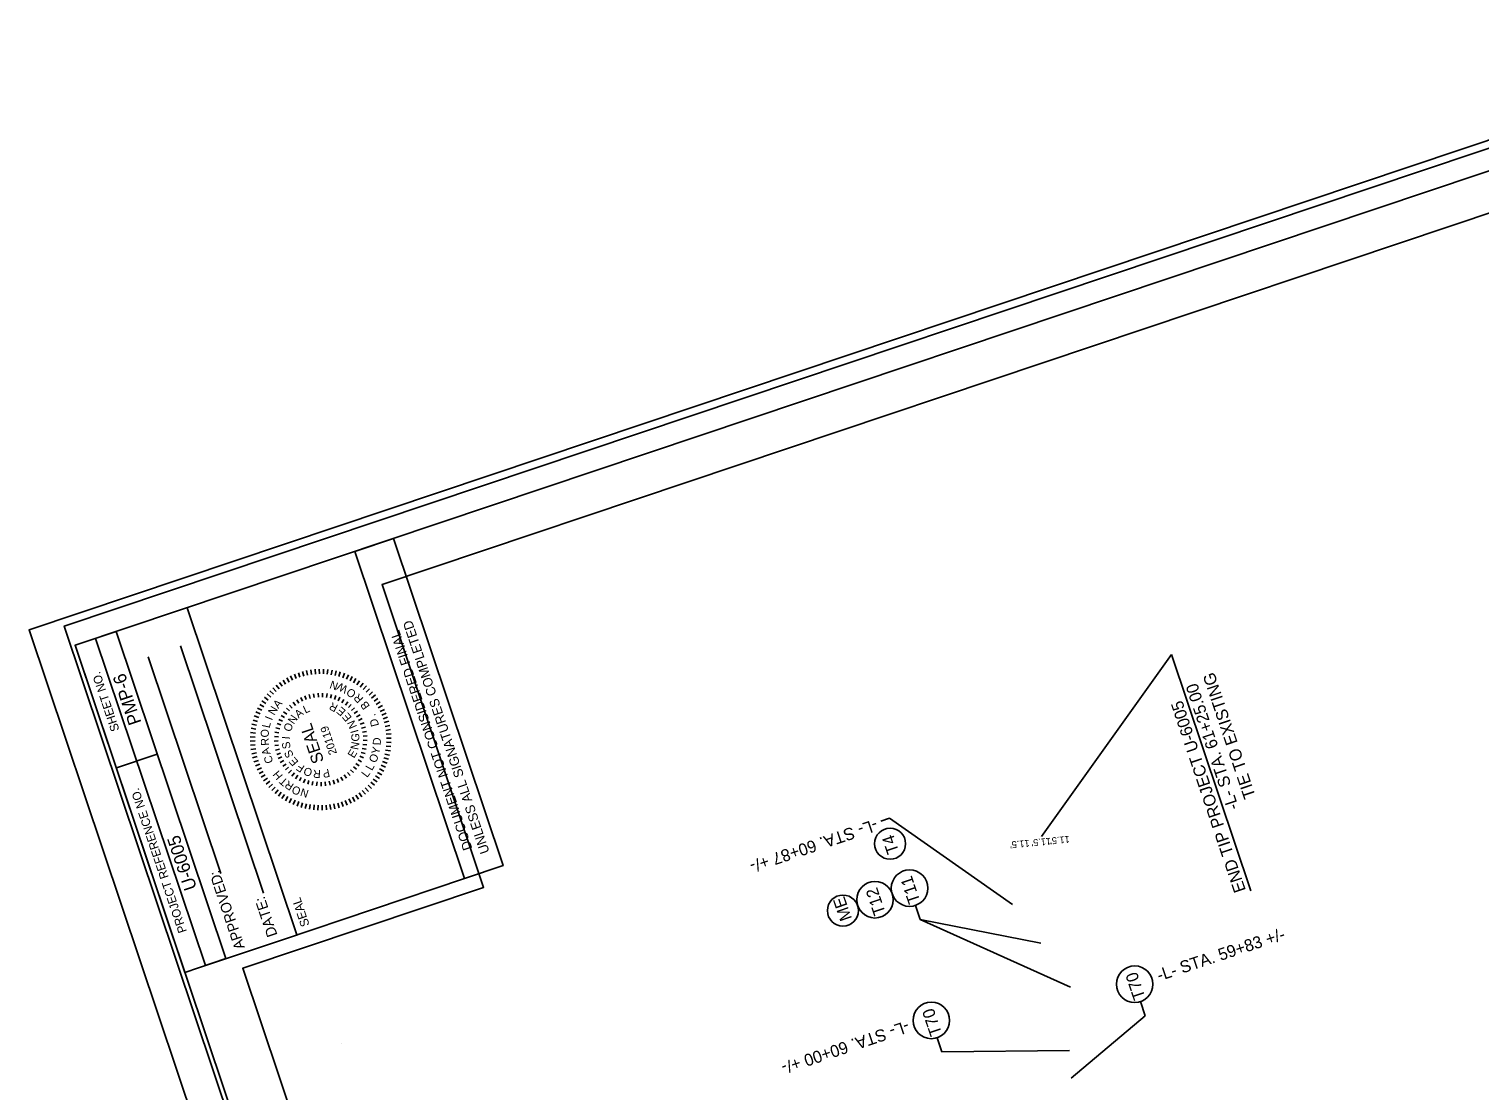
# Model space of a CAD drawing. Extents: x 1615436 to 1617119, y 903110 to 905145.
# Drawn here: x 1615436 to 1616278, y 904439 to 905055 of the extents above; entities that cross this region are included whole.
import ezdxf

# ---------------------------------------------------------------- set-up
doc = ezdxf.new("R2010")
doc.units = 0
for name, color, linetype in [('DEV BORDER CELL', 7, 'Continuous'), ('Old_Level_10', 7, 'Continuous'), ('Old_Level_4', 7, 'Continuous'), ('Prop Horizontal Alignment Curve and Spiral Data', 7, 'Continuous'), ('Prop Horizontal Alignment Station Label', 7, 'Continuous'), ('Sheet Data Field CELL', 7, 'Continuous'), ('Sheet Layout Plan Border', 7, 'Continuous'), ('Sheet North Arrow Point CELL', 7, 'Continuous'), ('Sheet Plan CELL', 7, 'Continuous'), ('Sheet Plot Border Inside CELL', 7, 'Continuous'), ('Sheet Plot Border Outside CELL', 7, 'Continuous'), ('Sheet Sticker Exception Certification CELL', 7, 'Continuous'), ('Sheet Title CELL', 7, 'Continuous'), ('Text', 7, 'Continuous')]:
    doc.layers.add(name, color=color, linetype=linetype)

msp = doc.modelspace()

# ---------------------------------------------------------------- linework, layer by layer
at = {"layer": 'DEV BORDER CELL'}
for p, q in [((1615599.8, 904683.37), (1615600.2, 904680.61)), ((1615602.25, 904683.64), (1615602.48, 904680.87)), ((1615604.72, 904683.77), (1615604.78, 904680.98)), ((1615607.19, 904683.75), (1615607.08, 904680.96)), ((1615609.65, 904683.57), (1615609.38, 904680.8)), ((1615581.65, 904676.06), (1615583.28, 904673.79)), ((1615583.7, 904677.44), (1615585.19, 904675.08)), ((1615585.83, 904678.7), (1615587.17, 904676.26)), ((1615588.02, 904679.82), (1615589.22, 904677.31)), ((1615590.28, 904680.81), (1615591.32, 904678.23)), ((1615592.6, 904681.67), (1615593.49, 904679.02)), ((1615594.97, 904682.38), (1615595.69, 904679.69)), ((1615597.37, 904682.95), (1615597.93, 904680.22)), ((1615612.1, 904683.25), (1615611.66, 904680.5)), ((1615614.53, 904682.78), (1615613.91, 904680.07)), ((1615616.92, 904682.17), (1615616.14, 904679.49)), ((1615619.27, 904681.41), (1615618.33, 904678.79)), ((1615621.57, 904680.51), (1615620.48, 904677.95)), ((1615623.81, 904679.48), (1615622.57, 904676.99)), ((1615625.98, 904678.31), (1615624.59, 904675.9)), ((1615628.09, 904677.01), (1615626.55, 904674.69)), ((1615630.1, 904675.59), (1615628.43, 904673.36)), ((1615572.87, 904667.44), (1615575.1, 904665.77)), ((1615574.41, 904669.37), (1615576.54, 904667.57)), ((1615576.07, 904671.2), (1615578.08, 904669.27)), ((1615577.84, 904672.93), (1615579.72, 904670.88)), ((1615579.7, 904674.55), (1615581.46, 904672.39)), ((1615594, 904667.24), (1615595, 904665.14)), ((1615596.41, 904668.24), (1615597.2, 904666.06)), ((1615598.89, 904669), (1615599.47, 904666.76)), ((1615601.72, 904667.22), (1615601.36, 904669.51)), ((1615604.04, 904669.8), (1615604.17, 904667.48)), ((1615606.64, 904669.82), (1615606.55, 904667.5)), ((1615609.23, 904669.59), (1615608.91, 904667.29)), ((1615611.79, 904669.11), (1615611.25, 904666.85)), ((1615614.29, 904668.39), (1615613.54, 904666.19)), ((1615616.71, 904667.43), (1615615.75, 904665.32)), ((1615632.03, 904674.05), (1615630.23, 904671.93)), ((1615633.87, 904672.4), (1615631.94, 904670.38)), ((1615635.59, 904670.63), (1615633.55, 904668.74)), ((1615637.22, 904668.77), (1615635.06, 904667)), ((1615638.72, 904666.81), (1615636.46, 904665.18)), ((1615567.95, 904658.91), (1615570.52, 904657.81)), ((1615568.99, 904661.15), (1615571.48, 904659.9)), ((1615570.16, 904663.32), (1615572.57, 904661.93)), ((1615571.45, 904665.42), (1615573.78, 904663.89)), ((1615584.02, 904659.08), (1615585.88, 904657.68)), ((1615585.68, 904661.08), (1615587.4, 904659.51)), ((1615587.53, 904662.91), (1615589.08, 904661.19)), ((1615589.55, 904664.56), (1615590.92, 904662.69)), ((1615591.71, 904666.01), (1615592.9, 904664.01)), ((1615619.02, 904666.24), (1615617.86, 904664.23)), ((1615621.21, 904664.83), (1615619.86, 904662.94)), ((1615623.26, 904663.22), (1615621.73, 904661.47)), ((1615625.13, 904661.41), (1615623.45, 904659.82)), ((1615626.83, 904659.44), (1615625, 904658.01)), ((1615640.1, 904664.76), (1615637.75, 904663.28)), ((1615641.36, 904662.64), (1615638.92, 904661.3)), ((1615642.48, 904660.44), (1615639.97, 904659.25)), ((1615643.48, 904658.18), (1615640.89, 904657.14)), ((1615565.68, 904651.86), (1615568.4, 904651.25)), ((1615566.3, 904654.26), (1615568.97, 904653.48)), ((1615567.05, 904656.6), (1615569.68, 904655.67)), ((1615579.51, 904649.76), (1615581.76, 904649.17)), ((1615580.29, 904652.24), (1615582.48, 904651.43)), ((1615581.31, 904654.63), (1615583.41, 904653.62)), ((1615582.56, 904656.92), (1615584.54, 904655.71)), ((1615628.33, 904657.31), (1615626.36, 904656.07)), ((1615629.61, 904655.05), (1615627.54, 904654)), ((1615630.67, 904652.67), (1615628.51, 904651.83)), ((1615631.5, 904650.2), (1615629.26, 904649.57)), ((1615644.33, 904655.86), (1615641.69, 904654.98)), ((1615645.04, 904653.5), (1615642.35, 904652.78)), ((1615645.61, 904651.1), (1615642.88, 904650.54)), ((1615564.7, 904642.06), (1615567.49, 904642.12)), ((1615564.72, 904644.53), (1615567.51, 904644.41)), ((1615564.9, 904646.99), (1615567.67, 904646.71)), ((1615565.21, 904649.44), (1615567.97, 904648.99)), ((1615578.64, 904642.02), (1615580.96, 904642.1)), ((1615578.68, 904644.62), (1615581, 904644.48)), ((1615578.97, 904647.21), (1615581.26, 904646.84)), ((1615632.08, 904647.67), (1615629.8, 904647.25)), ((1615630.1, 904644.88), (1615632.42, 904645.07)), ((1615632.5, 904642.48), (1615630.18, 904642.52)), ((1615646.03, 904648.67), (1615643.28, 904648.27)), ((1615646.31, 904646.21), (1615643.53, 904645.98)), ((1615646.41, 904641.28), (1615643.62, 904641.39)), ((1615646.43, 904643.74), (1615643.64, 904643.68)), ((1615564.82, 904639.59), (1615567.6, 904639.82)), ((1615565.1, 904637.14), (1615567.85, 904637.53)), ((1615565.52, 904634.71), (1615568.25, 904635.27)), ((1615566.09, 904632.3), (1615568.78, 904633.03)), ((1615578.85, 904639.42), (1615581.15, 904639.73)), ((1615579.31, 904636.87), (1615581.57, 904637.38)), ((1615580.02, 904634.36), (1615582.22, 904635.09)), ((1615582.22, 904635.09), (1615580.02, 904634.36)), ((1615580.96, 904631.93), (1615583.08, 904632.88)), ((1615630.35, 904632.35), (1615628.22, 904633.26)), ((1615631.26, 904634.8), (1615629.04, 904635.49)), ((1615631.92, 904637.31), (1615629.65, 904637.8)), ((1615632.33, 904639.88), (1615630.02, 904640.14)), ((1615645.45, 904633.94), (1615642.73, 904634.55)), ((1615645.92, 904636.37), (1615643.16, 904636.81)), ((1615646.23, 904638.81), (1615643.46, 904639.09)), ((1615566.8, 904629.94), (1615569.44, 904630.82)), ((1615567.65, 904627.62), (1615570.24, 904628.66)), ((1615568.65, 904625.36), (1615571.16, 904626.55)), ((1615569.77, 904623.16), (1615572.21, 904624.51)), ((1615582.13, 904629.61), (1615584.15, 904630.75)), ((1615583.52, 904627.41), (1615585.43, 904628.74)), ((1615585.12, 904625.35), (1615586.89, 904626.87)), ((1615586.91, 904623.46), (1615588.52, 904625.14)), ((1615624.55, 904623.79), (1615622.91, 904625.43)), ((1615626.3, 904625.7), (1615624.52, 904627.19)), ((1615627.87, 904627.79), (1615625.95, 904629.09)), ((1615629.22, 904630.01), (1615627.18, 904631.12)), ((1615642.14, 904624.66), (1615639.65, 904625.9)), ((1615643.18, 904626.9), (1615640.61, 904627.99)), ((1615644.08, 904629.2), (1615641.45, 904630.13)), ((1615644.83, 904631.55), (1615642.16, 904632.32)), ((1615571.03, 904621.04), (1615573.38, 904622.53)), ((1615572.41, 904618.99), (1615574.67, 904620.62)), ((1615573.91, 904617.03), (1615576.07, 904618.8)), ((1615575.54, 904615.17), (1615577.58, 904617.06)), ((1615588.88, 904621.75), (1615590.32, 904623.58)), ((1615591, 904620.24), (1615592.25, 904622.2)), ((1615593.25, 904618.94), (1615594.31, 904621.01)), ((1615595.62, 904617.87), (1615596.48, 904620.02)), ((1615598.08, 904617.02), (1615598.73, 904619.25)), ((1615600.61, 904616.42), (1615601.04, 904618.7)), ((1615603.2, 904616.06), (1615603.4, 904618.38)), ((1615605.8, 904615.96), (1615605.77, 904618.29)), ((1615608.39, 904616.11), (1615608.15, 904618.42)), ((1615610.97, 904616.51), (1615610.5, 904618.78)), ((1615613.49, 904617.15), (1615612.81, 904619.37)), ((1615615.94, 904618.04), (1615615.05, 904620.18)), ((1615618.29, 904619.16), (1615617.19, 904621.2)), ((1615620.52, 904620.49), (1615619.24, 904622.42)), ((1615622.62, 904622.04), (1615621.15, 904623.84)), ((1615635.06, 904614.6), (1615633.05, 904616.53)), ((1615636.72, 904616.43), (1615634.59, 904618.24)), ((1615638.26, 904618.36), (1615636.03, 904620.03)), ((1615639.68, 904620.38), (1615637.35, 904621.92)), ((1615640.97, 904622.48), (1615638.56, 904623.87)), ((1615577.26, 904613.41), (1615579.19, 904615.42)), ((1615579.1, 904611.75), (1615580.9, 904613.88)), ((1615581.03, 904610.21), (1615582.7, 904612.44)), ((1615583.04, 904608.79), (1615584.58, 904611.11)), ((1615585.15, 904607.49), (1615586.54, 904609.91)), ((1615587.32, 904606.33), (1615588.56, 904608.82)), ((1615589.56, 904605.29), (1615590.65, 904607.85)), ((1615620.85, 904604.99), (1615619.81, 904607.57)), ((1615623.11, 904605.98), (1615621.91, 904608.5)), ((1615625.3, 904607.11), (1615623.96, 904609.55)), ((1615627.43, 904608.36), (1615625.94, 904610.72)), ((1615629.48, 904609.75), (1615627.85, 904612.01)), ((1615631.43, 904611.25), (1615629.67, 904613.41)), ((1615633.29, 904612.87), (1615631.41, 904614.92)), ((1615591.86, 904604.39), (1615592.8, 904607.02)), ((1615594.21, 904603.63), (1615594.99, 904606.31)), ((1615596.6, 904603.02), (1615597.22, 904605.74)), ((1615599.03, 904602.55), (1615599.47, 904605.3)), ((1615601.48, 904602.23), (1615601.75, 904605)), ((1615603.94, 904602.06), (1615604.05, 904604.84)), ((1615606.41, 904602.03), (1615606.35, 904604.82)), ((1615608.88, 904602.16), (1615608.65, 904604.94)), ((1615611.33, 904602.43), (1615610.93, 904605.19)), ((1615613.76, 904602.86), (1615613.2, 904605.58)), ((1615616.16, 904603.42), (1615615.44, 904606.11)), ((1615618.53, 904604.14), (1615617.64, 904606.78))]:
    msp.add_line(p, q, dxfattribs=at)
at = {"layer": 'Old_Level_10'}
for p, q in [((1615572.45, 904553.86), (1615524.33, 904697.3)), ((1615547.63, 904565.24), (1615505.46, 904690.97))]:
    msp.add_line(p, q, dxfattribs=at)
at = {"layer": 'Prop Horizontal Alignment Curve and Spiral Data'}
msp.add_line((1616144.77, 904555.27), (1616098.85, 904692.18), dxfattribs=at)
at = {"layer": 'Prop Horizontal Alignment Station Label'}
msp.add_line((1616023.42, 904586.81), (1616098.85, 904692.18), dxfattribs=at)
at = {"layer": 'Sheet Layout Plan Border'}
msp.add_lwpolyline([(1616672.58, 903656.2), (1616919.77, 903656.8), (1616590.65, 904611.24), (1616386.84, 904624.44), (1616334.81, 904821.64), (1616466, 905009.57), (1615641.09, 904732.87), (1615700.02, 904557.19), (1615560.35, 904510.33), (1615954.19, 903336.21)], close=True, dxfattribs=at)
at = {"layer": 'Sheet North Arrow Point CELL'}
msp.add_line((1615617.56, 904466.62), (1615617.56, 904466.62), dxfattribs=at)
at = {"layer": 'Sheet Plan CELL'}
for p, q in [((1615538.66, 904511.93), (1615475.05, 904701.6)), ((1615550.54, 904515.93), (1615486.9, 904705.57)), ((1615550.54, 904515.93), (1615486.9, 904705.57)), ((1615487.07, 904626.5), (1615510.76, 904634.49))]:
    msp.add_line(p, q, dxfattribs=at)
for points in [[(1615463.14, 904697.64), (1615940.18, 903275.48), (1616935.67, 903609.4), (1616458.64, 905031.54)], [(1615526.76, 904507.95), (1615463.14, 904697.64), (1615486.9, 904705.57), (1615550.54, 904515.93)]]:
    msp.add_lwpolyline(points, close=True, dxfattribs=at)
at = {"layer": 'Sheet Plot Border Inside CELL'}
msp.add_lwpolyline([(1616986.86, 903464.68), (1616457.04, 905044.17), (1615456.82, 904708.68), (1615986.63, 903129.17)], close=True, dxfattribs=at)
at = {"layer": 'Sheet Plot Border Outside CELL'}
msp.add_lwpolyline([(1617009.96, 903458.71), (1616474.57, 905054.81), (1615436.42, 904706.58), (1615971.81, 903110.48)], close=True, dxfattribs=at)
at = {"layer": 'Sheet Sticker Exception Certification CELL'}
msp.add_lwpolyline([(1615689.01, 904562.36), (1615625.39, 904752.02), (1615647.66, 904759.5), (1615711.28, 904569.83)], close=True, dxfattribs=at)
at = {"layer": 'Sheet Title CELL'}
for p, q in [((1615625.39, 904752.02), (1615689.01, 904562.36)), ((1615591.68, 904529.71), (1615528.06, 904719.38)), ((1615689.01, 904562.36), (1615583.39, 904526.93)), ((1615583.39, 904526.93), (1615538.66, 904511.93))]:
    msp.add_line(p, q, dxfattribs=at)
at = {"layer": 'Text'}
for p, q in [((1615935.27, 904597.3), (1615930.24, 904595.61)), ((1616006.68, 904547.35), (1615935.27, 904597.3)), ((1615953.08, 904538.53), (1615950.31, 904546.77)), ((1616040.35, 904499.44), (1615953.08, 904538.53)), ((1616022.98, 904524.88), (1615953.08, 904538.53)), ((1616083.62, 904482.84), (1616080.85, 904491.08)), ((1616040.66, 904446.67), (1616083.62, 904482.84)), ((1615965.71, 904461.83), (1615962.95, 904470.08)), ((1616039.73, 904462.62), (1615965.71, 904461.83))]:
    msp.add_line(p, q, dxfattribs=at)
for centre, radius in [((1615935.68, 904582.57), 9.01), ((1615946.95, 904556.8), 10.58), ((1615926.89, 904550.07), 10.58), ((1615908.35, 904543.76), 9.01), ((1616077.49, 904501.11), 10.58), ((1615959.58, 904480.11), 10.58)]:
    msp.add_circle(centre, radius, dxfattribs=at)

# ---------------------------------------------------------------- texts
at = {"layer": 'DEV BORDER CELL'}
for s, height, rotation, p in [('N', 4.64, 160.69721, (1615616.07, 904675.69)), ('W', 4.64, 151.81458, (1615621.73, 904673.48)), ('O', 4.64, 142.93195, (1615626.49, 904670.25)), ('R', 4.64, 134.10933, (1615630.57, 904666.76)), ('N', 4.64, 58.77478, (1615578.64, 904656.63)), ('A', 4.64, 49.00725, (1615580.92, 904660.62)), ('A', 4.64, 39.65705, (1615592.73, 904655.06)), ('L', 4.64, 24.3608, (1615596.61, 904657.94)), ('R', 4.64, 153.05504, (1615615.97, 904662.77)), ('E', 4.64, 139.28396, (1615620.44, 904659.6)), ('E', 4.64, 129.29808, (1615623.83, 904655.72)), ('B', 4.64, 125.10677, (1615634.27, 904662.35)), ('L', 4.64, 77.64471, (1615575.94, 904649.33)), ('I', 4.64, 68.06924, (1615577.31, 904653.73)), ('O', 4.64, 70.24954, (1615588.12, 904647.07)), ('N', 4.64, 54.95329, (1615589.94, 904651.44)), ('SEAL', 6.965, 108.49015, (1615607.54, 904630.4)), ('20119', 4.64, 108.49015, (1615615.03, 904634.92)), ('N', 4.64, 113.90601, (1615626.67, 904650.47)), ('D', 4.64, 104.58011, (1615639.4, 904651.12)), ('.', 4.64, 112.32245, (1615637.58, 904656.68)), ('O', 4.64, 90.781, (1615575.48, 904644.2)), ('R', 4.64, 93.83781, (1615575.64, 904639.51)), ('I', 4.64, 85.54578, (1615587.6, 904642.94)), ('S', 4.64, 100.84203, (1615588.21, 904637.95)), ('I', 4.64, 106.27635, (1615627.53, 904647.44)), ('N', 4.64, 79.41532, (1615627.25, 904636.73)), ('G', 4.64, 88.18155, (1615627.87, 904641.72)), ('D', 4.64, 86.7848, (1615640.31, 904639.52)), ('A', 4.64, 105.84712, (1615576.55, 904634.63)), ('C', 4.64, 105.84712, (1615578.07, 904629.79)), ('S', 4.64, 116.13828, (1615590.05, 904633.68)), ('E', 4.64, 131.43452, (1615592.94, 904630.05)), ('E', 4.64, 58.56024, (1615624.81, 904631.8)), ('O', 4.64, 69.13973, (1615637.62, 904629.08)), ('Y', 4.64, 77.81232, (1615639.35, 904634.11)), ('H', 4.64, 129.55781, (1615583.82, 904621.98)), ('F', 4.64, 146.73077, (1615596.61, 904627.36)), ('O', 4.64, 162.02701, (1615601.13, 904625.62)), ('R', 4.64, 177.32326, (1615605.67, 904625.2)), ('P', 4.64, 192.61951, (1615610.25, 904625.99)), ('L', 4.64, 60.49698, (1615635.27, 904624.58)), ('T', 4.64, 138.98975, (1615586.92, 904619.08)), ('R', 4.64, 147.15072, (1615590.37, 904616.94)), ('L', 4.64, 52.42517, (1615632.4, 904620.59)), ('O', 4.64, 160.20745, (1615594.4, 904614.75)), ('N', 4.64, 162.16688, (1615598.97, 904613.46))]:
    msp.add_text(s, height=height, rotation=rotation, dxfattribs=at).set_placement(p)
at = {"layer": 'Old_Level_10'}
msp.add_text('SEAL', height=5.094, rotation=108.53811, dxfattribs=at).set_placement((1615599.16, 904535.41))
at = {"layer": 'Old_Level_4'}
for s, p in [('APPROVED:', (1615561.72, 904522.39)), ('DATE:', (1615580.52, 904529.67))]:
    msp.add_text(s, height=6.11, rotation=108.53811, dxfattribs=at).set_placement(p)
at = {"layer": 'Prop Horizontal Alignment Station Label'}
for s, p in [('-L- STA. 61+25.00', (1616137.98, 904603.38)), ('TIE TO EXISTING', (1616147.76, 904610.02)), ('END TIP PROJECT U-6005', (1616142.01, 904555.6))]:
    msp.add_text(s, height=7, rotation=108.54317, dxfattribs=at).set_placement(p)
at = {"layer": 'Sheet Data Field CELL'}
for s, p in [('PMP-6', (1615501.64, 904652.84)), ('U-6005', (1615533.87, 904556.94))]:
    msp.add_text(s, height=7.5, rotation=108.54318, dxfattribs=at).set_placement(p)
at = {"layer": 'Sheet Plan CELL'}
for s, height, p in [('SHEET NO.', 5, (1615488.91, 904648.58)), ('PROJECT REFERENCE NO.', 5.0001, (1615527.97, 904531.77))]:
    msp.add_text(s, height=height, rotation=108.54318, dxfattribs=at).set_placement(p)
at = {"layer": 'Sheet Sticker Exception Certification CELL'}
for s, p in [('UNLESS ALL SIGNATURES COMPLETED', (1615703.5, 904577.78)), ('DOCUMENT NOT CONSIDERED FINAL', (1615693.55, 904579.79))]:
    msp.add_text(s, height=5.4984, rotation=108.54317, dxfattribs=at).set_placement(p)
at = {"layer": 'Text'}
for s, height, rotation, p in [('-L- STA. 60+87 +/-', 7, 198.54317, (1615927.09, 904596.98)), ('T4', 7, 108.51236, (1615940.92, 904577.96)), ("11.5'", 4, 185.06218, (1616016.37, 904584.82)), ("11.5'", 4, 185.06218, (1616028.83, 904586.01)), ("11.5'", 4, 185.06218, (1616039.64, 904587.12)), ('T12', 7, 108.54317, (1615933.18, 904542.42)), ('T11', 7, 108.54317, (1615953.25, 904549.15)), ('ME', 7, 109.13879, (1615913.63, 904539.21)), ('-L- STA. 59+83 +/-', 7, 18.36073, (1616091.74, 904502.82)), ('T70', 7, 108.54317, (1616083.78, 904493.46)), ('T70', 7, 108.54317, (1615965.88, 904472.45)), ('-L- STA. 60+00 +/-', 7, 198.54317, (1615945.42, 904480.16))]:
    msp.add_text(s, height=height, rotation=rotation, dxfattribs=at).set_placement(p)

doc.saveas('drawing.dxf')
